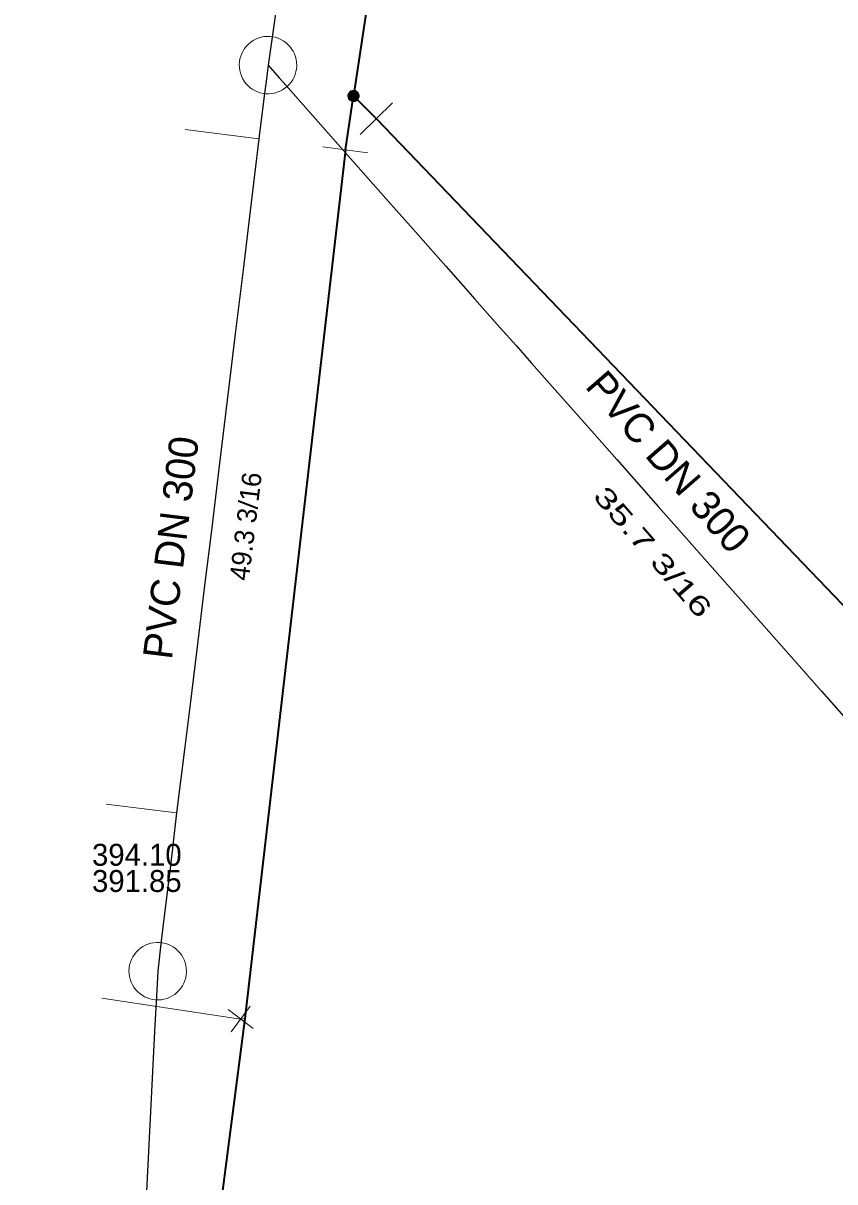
# Model space of a CAD drawing. Extents: x -772952 to -772403, y -1033777 to -1033210.
# Drawn here: x -772626.79 to -772593.44, y -1033420.99 to -1033373.41 of the extents above; entities that cross this region are included whole.
import ezdxf

# ---------------------------------------------------------------- set-up
doc = ezdxf.new("R2010")
doc.units = 0
doc.header["$LTSCALE"] = 0.36
for name, color, linetype, lineweight in [('15', 7, 'Continuous', 13), ('16', 7, 'Continuous', 35), ('2', 7, 'Continuous', 25), ('4', 7, 'Continuous', 13), ('57', 7, 'Continuous', 13), ('59', 7, 'Continuous', 13)]:
    doc.layers.add(name, color=color, linetype=linetype, lineweight=lineweight)
doc.layers.add('3', color=7, linetype='Continuous')
doc.layers.add('6', color=7, linetype='Continuous')

msp = doc.modelspace()

# ---------------------------------------------------------------- linework, layer by layer
at = {"layer": '15'}
for p, q in [((-772612.943, -1033377.984), (-772611.613, -1033376.68)), ((-772612.625, -1033378.736), (-772614.471, -1033378.491)), ((-772617.468, -1033413.787), (-772618.243, -1033414.833)), ((-772617.337, -1033414.692), (-772618.373, -1033413.922))]:
    msp.add_line(p, q, dxfattribs=at)
for points in [[(-772612.985, -1033376.397), (-772612.991, -1033376.345), (-772613.008, -1033376.295), (-772613.037, -1033376.251), (-772613.074, -1033376.214), (-772613.119, -1033376.187), (-772613.169, -1033376.17), (-772613.222, -1033376.166), (-772613.274, -1033376.173), (-772613.323, -1033376.192), (-772613.366, -1033376.221), (-772613.402, -1033376.26), (-772613.428, -1033376.305), (-772613.444, -1033376.356), (-772613.447, -1033376.408), (-772613.439, -1033376.46), (-772613.419, -1033376.509), (-772613.388, -1033376.552), (-772613.349, -1033376.586), (-772613.303, -1033376.612), (-772613.252, -1033376.626), (-772613.199, -1033376.628), (-772613.148, -1033376.618), (-772613.1, -1033376.597), (-772613.057, -1033376.566), (-772613.023, -1033376.525), (-772612.999, -1033376.479), (-772612.987, -1033376.428)], [(-772613.015, -1033376.397), (-772613.021, -1033376.348), (-772613.038, -1033376.302), (-772613.066, -1033376.262), (-772613.103, -1033376.23), (-772613.147, -1033376.208), (-772613.195, -1033376.197), (-772613.244, -1033376.197), (-772613.291, -1033376.21), (-772613.334, -1033376.234), (-772613.37, -1033376.267), (-772613.397, -1033376.308), (-772613.413, -1033376.355), (-772613.417, -1033376.404), (-772613.41, -1033376.452), (-772613.391, -1033376.497), (-772613.361, -1033376.537), (-772613.323, -1033376.568), (-772613.279, -1033376.588), (-772613.231, -1033376.598), (-772613.182, -1033376.596), (-772613.135, -1033376.581), (-772613.092, -1033376.556), (-772613.058, -1033376.522), (-772613.032, -1033376.48), (-772613.018, -1033376.433)], [(-772613.045, -1033376.397), (-772613.051, -1033376.352), (-772613.068, -1033376.31), (-772613.096, -1033376.275), (-772613.132, -1033376.248), (-772613.174, -1033376.231), (-772613.219, -1033376.226), (-772613.264, -1033376.232), (-772613.305, -1033376.251), (-772613.34, -1033376.279), (-772613.367, -1033376.316), (-772613.383, -1033376.358), (-772613.387, -1033376.403), (-772613.38, -1033376.448), (-772613.361, -1033376.489), (-772613.332, -1033376.523), (-772613.295, -1033376.549), (-772613.252, -1033376.565), (-772613.207, -1033376.568), (-772613.162, -1033376.56), (-772613.122, -1033376.54), (-772613.088, -1033376.511), (-772613.062, -1033376.473), (-772613.048, -1033376.43)], [(-772613.075, -1033376.397), (-772613.08, -1033376.356), (-772613.098, -1033376.319), (-772613.125, -1033376.288), (-772613.16, -1033376.267), (-772613.2, -1033376.256), (-772613.241, -1033376.258), (-772613.28, -1033376.271), (-772613.314, -1033376.295), (-772613.339, -1033376.327), (-772613.354, -1033376.365), (-772613.357, -1033376.406), (-772613.349, -1033376.446), (-772613.329, -1033376.482), (-772613.3, -1033376.511), (-772613.263, -1033376.53), (-772613.223, -1033376.538), (-772613.182, -1033376.534), (-772613.144, -1033376.519), (-772613.112, -1033376.493), (-772613.089, -1033376.459), (-772613.076, -1033376.42)], [(-772613.105, -1033376.397), (-772613.11, -1033376.361), (-772613.128, -1033376.329), (-772613.154, -1033376.304), (-772613.188, -1033376.289), (-772613.224, -1033376.286), (-772613.259, -1033376.294), (-772613.29, -1033376.314), (-772613.313, -1033376.342), (-772613.326, -1033376.376), (-772613.326, -1033376.413), (-772613.315, -1033376.448), (-772613.294, -1033376.477), (-772613.264, -1033376.498), (-772613.229, -1033376.508), (-772613.192, -1033376.506), (-772613.158, -1033376.492), (-772613.131, -1033376.469), (-772613.112, -1033376.437), (-772613.105, -1033376.402)], [(-772613.135, -1033376.397), (-772613.14, -1033376.366), (-772613.157, -1033376.34), (-772613.183, -1033376.323), (-772613.213, -1033376.316), (-772613.244, -1033376.32), (-772613.271, -1033376.337), (-772613.289, -1033376.361), (-772613.297, -1033376.392), (-772613.293, -1033376.422), (-772613.278, -1033376.45), (-772613.254, -1033376.469), (-772613.224, -1033376.478), (-772613.193, -1033376.475), (-772613.165, -1033376.461), (-772613.145, -1033376.437), (-772613.135, -1033376.408)], [(-772613.165, -1033376.397), (-772613.17, -1033376.373), (-772613.187, -1033376.355), (-772613.21, -1033376.346), (-772613.234, -1033376.349), (-772613.255, -1033376.363), (-772613.266, -1033376.385), (-772613.266, -1033376.41), (-772613.254, -1033376.431), (-772613.234, -1033376.445), (-772613.209, -1033376.448), (-772613.186, -1033376.439), (-772613.17, -1033376.421)], [(-772613.195, -1033376.397), (-772613.2, -1033376.382), (-772613.215, -1033376.376), (-772613.23, -1033376.38), (-772613.237, -1033376.394), (-772613.233, -1033376.409), (-772613.22, -1033376.418), (-772613.205, -1033376.415), (-772613.195, -1033376.403)]]:
    msp.add_lwpolyline(points, close=True, dxfattribs=at)
at = {"layer": '16'}
for p, q in [((-772613.548, -1033378.614), (-772613.215, -1033376.396)), ((-772613.215, -1033376.396), (-772612.278, -1033377.333))]:
    msp.add_line(p, q, dxfattribs=at)
for points in [[(-772611.37, -1033342.94), (-772612.62, -1033372.379), (-772613.215, -1033376.396)], [(-772612.278, -1033377.333), (-772580.497, -1033410.436), (-772578.041, -1033413.37), (-772577.006, -1033414.5), (-772569.058, -1033423.229), (-772559.875, -1033433.313), (-772549.379, -1033444.412), (-772529.995, -1033467.089), (-772529.738, -1033467.366), (-772517.883, -1033480.75), (-772495.067, -1033506.688), (-772494.015, -1033507.864), (-772482.842, -1033520.835)], [(-772613.548, -1033378.614), (-772617.688, -1033414.284), (-772618.8, -1033422.937), (-772620.62, -1033437.085), (-772622.445, -1033453.872), (-772624.496, -1033472.436), (-772624.78, -1033475.004), (-772624.872, -1033476.41)]]:
    msp.add_lwpolyline(points, dxfattribs=at)
at = {"layer": '2'}
for points in [[(-772613.36, -1033352.04), (-772613.463, -1033352.747), (-772613.521, -1033353.145), (-772613.969, -1033356.213), (-772614.381, -1033359.036), (-772615.085, -1033363.859), (-772615.734, -1033368.305), (-772616.142, -1033371.106), (-772616.478, -1033373.404), (-772616.576, -1033374.075), (-772616.73, -1033375.13)], [(-772616.73, -1033375.13), (-772616.769, -1033375.456), (-772616.811, -1033375.799), (-772616.847, -1033376.094), (-772616.883, -1033376.392), (-772617.102, -1033378.153), (-772617.459, -1033381.118), (-772617.754, -1033383.533), (-772618.075, -1033386.167), (-772618.352, -1033388.445), (-772618.709, -1033391.37), (-772619.072, -1033394.348), (-772619.335, -1033396.505), (-772619.655, -1033399.135), (-772619.928, -1033401.374), (-772620.155, -1033403.24), (-772620.485, -1033405.843), (-772620.737, -1033408.01), (-772620.976, -1033409.971), (-772621.114, -1033411.103), (-772621.262, -1033412.344)], [(-772616.73, -1033375.13), (-772616.271, -1033375.648), (-772616.11, -1033375.83), (-772615.491, -1033376.53), (-772614.672, -1033377.456), (-772613.027, -1033379.317), (-772611.682, -1033380.837), (-772610.882, -1033381.741), (-772610.155, -1033382.562), (-772609.421, -1033383.392), (-772608.708, -1033384.198), (-772608.23, -1033384.739), (-772607.816, -1033385.207), (-772607.201, -1033385.903), (-772606.539, -1033386.65), (-772605.904, -1033387.369), (-772605.167, -1033388.202), (-772603.744, -1033389.81), (-772602.404, -1033391.326), (-772600.698, -1033393.254), (-772599.63, -1033394.462), (-772598.474, -1033395.769), (-772597.417, -1033396.964), (-772595.84, -1033398.746), (-772593.987, -1033400.841), (-772592.452, -1033402.577)], [(-772621.262, -1033412.344), (-772621.314, -1033413.381), (-772621.374, -1033414.563), (-772621.814, -1033423.299), (-772622.145, -1033429.861), (-772626.646, -1033464.096), (-772626.699, -1033464.335), (-772626.739, -1033464.518), (-772626.79, -1033464.75)]]:
    msp.add_lwpolyline(points, dxfattribs=at)
at = {"layer": '4'}
for points in [[(-772615.549, -1033375.129), (-772615.556, -1033375.01), (-772615.574, -1033374.893), (-772615.603, -1033374.777), (-772615.644, -1033374.666), (-772615.696, -1033374.559), (-772615.759, -1033374.458), (-772615.831, -1033374.363), (-772615.913, -1033374.277), (-772616.003, -1033374.199), (-772616.101, -1033374.13), (-772616.204, -1033374.072), (-772616.313, -1033374.025), (-772616.427, -1033373.988), (-772616.543, -1033373.963), (-772616.661, -1033373.951), (-772616.78, -1033373.95), (-772616.899, -1033373.961), (-772617.015, -1033373.984), (-772617.129, -1033374.018), (-772617.239, -1033374.064), (-772617.343, -1033374.121), (-772617.442, -1033374.188), (-772617.532, -1033374.264), (-772617.616, -1033374.349), (-772617.69, -1033374.443), (-772617.754, -1033374.543), (-772617.808, -1033374.649), (-772617.851, -1033374.76), (-772617.883, -1033374.874), (-772617.902, -1033374.992), (-772617.91, -1033375.111), (-772617.906, -1033375.229), (-772617.89, -1033375.347), (-772617.862, -1033375.463), (-772617.823, -1033375.575), (-772617.772, -1033375.683), (-772617.711, -1033375.785), (-772617.64, -1033375.881), (-772617.559, -1033375.968), (-772617.471, -1033376.048), (-772617.375, -1033376.118), (-772617.272, -1033376.178), (-772617.164, -1033376.227), (-772617.051, -1033376.265), (-772616.934, -1033376.291), (-772616.817, -1033376.306), (-772616.698, -1033376.309), (-772616.58, -1033376.3), (-772616.462, -1033376.279), (-772616.348, -1033376.246), (-772616.238, -1033376.202), (-772616.132, -1033376.147), (-772616.032, -1033376.081), (-772615.94, -1033376.006), (-772615.856, -1033375.922), (-772615.781, -1033375.83), (-772615.715, -1033375.731), (-772615.659, -1033375.626), (-772615.615, -1033375.516), (-772615.581, -1033375.402), (-772615.559, -1033375.285), (-772615.549, -1033375.166)], [(-772620.081, -1033412.344), (-772620.088, -1033412.225), (-772620.106, -1033412.108), (-772620.135, -1033411.992), (-772620.176, -1033411.881), (-772620.228, -1033411.774), (-772620.291, -1033411.673), (-772620.364, -1033411.578), (-772620.445, -1033411.492), (-772620.535, -1033411.414), (-772620.633, -1033411.345), (-772620.736, -1033411.287), (-772620.845, -1033411.24), (-772620.959, -1033411.203), (-772621.075, -1033411.178), (-772621.193, -1033411.166), (-772621.312, -1033411.165), (-772621.431, -1033411.176), (-772621.547, -1033411.199), (-772621.661, -1033411.233), (-772621.771, -1033411.279), (-772621.875, -1033411.336), (-772621.974, -1033411.403), (-772622.065, -1033411.479), (-772622.148, -1033411.564), (-772622.222, -1033411.658), (-772622.286, -1033411.758), (-772622.34, -1033411.864), (-772622.383, -1033411.975), (-772622.415, -1033412.089), (-772622.434, -1033412.207), (-772622.442, -1033412.326), (-772622.438, -1033412.444), (-772622.422, -1033412.562), (-772622.394, -1033412.678), (-772622.355, -1033412.79), (-772622.304, -1033412.898), (-772622.243, -1033413), (-772622.172, -1033413.096), (-772622.092, -1033413.183), (-772622.003, -1033413.263), (-772621.907, -1033413.333), (-772621.804, -1033413.393), (-772621.696, -1033413.442), (-772621.583, -1033413.48), (-772621.467, -1033413.506), (-772621.349, -1033413.521), (-772621.23, -1033413.524), (-772621.112, -1033413.515), (-772620.994, -1033413.494), (-772620.88, -1033413.461), (-772620.77, -1033413.417), (-772620.664, -1033413.362), (-772620.565, -1033413.296), (-772620.472, -1033413.221), (-772620.388, -1033413.137), (-772620.313, -1033413.045), (-772620.247, -1033412.946), (-772620.191, -1033412.841), (-772620.147, -1033412.731), (-772620.113, -1033412.617), (-772620.092, -1033412.5), (-772620.081, -1033412.381)]]:
    msp.add_lwpolyline(points, close=True, dxfattribs=at)
at = {"layer": '57'}
for p, q in [((-772617.102, -1033378.153), (-772620.14, -1033377.78)), ((-772620.485, -1033405.843), (-772623.38, -1033405.49))]:
    msp.add_line(p, q, dxfattribs=at)
at = {"layer": '59'}
msp.add_lwpolyline([(-772617.688, -1033414.284), (-772617.855, -1033414.309), (-772623.553, -1033413.451)], dxfattribs=at)

# ---------------------------------------------------------------- texts
at = {"layer": '3'}
for s, height, rotation, p in [('PVC DN 300', 1.2, 311, (-772603.741, -1033388.346)), ('PVC DN 300', 1.2, 83, (-772620.685, -1033399.575)), ('49.3 3/16', 0.8, 83, (-772617.522, -1033396.334))]:
    msp.add_text(s, height=height, rotation=rotation, dxfattribs=at).set_placement(p)
at = {"layer": '3', "width": 1.5}
msp.add_text('35.7 3/16', height=0.8, rotation=311, dxfattribs=at).set_placement((-772603.414, -1033392.862))
at = {"layer": '6'}
for s, p in [('394.10', (-772623.96, -1033408.012)), ('391.85', (-772623.96, -1033409.089))]:
    msp.add_text(s, height=0.9, dxfattribs=at).set_placement(p)

doc.saveas('drawing.dxf')
